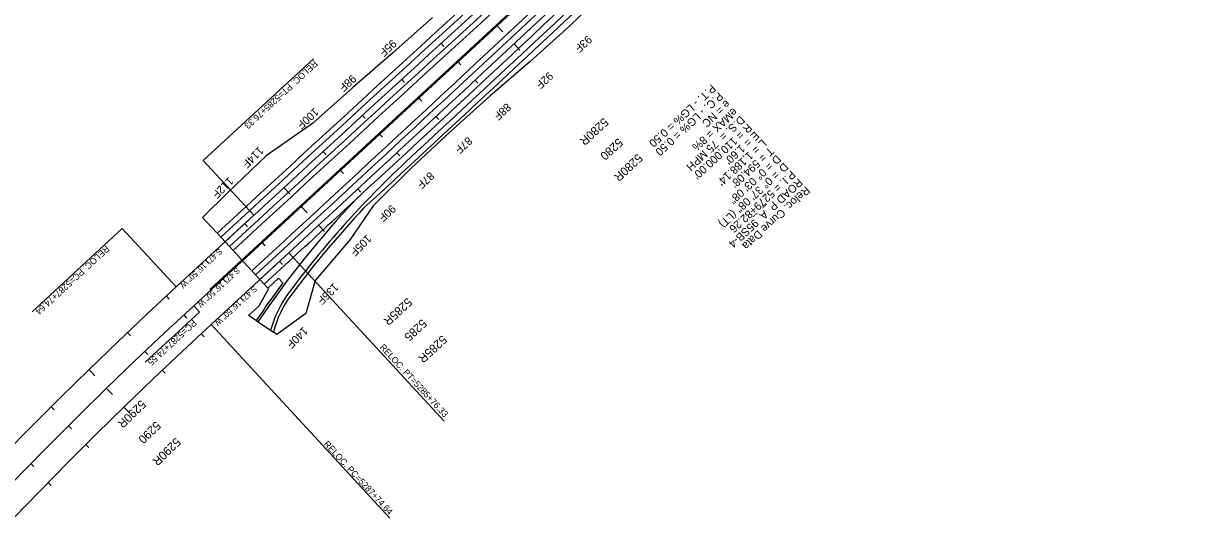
# Model space of a CAD drawing. Extents: x 2160876 to 2175625, y 601634 to 617693.
# Drawn here: x 2163386 to 2165605, y 605458 to 606388 of the extents above; entities that cross this region are included whole.
import ezdxf

# ---------------------------------------------------------------- set-up
doc = ezdxf.new("R2010")
doc.units = 0
for name, color, linetype in [('RD_HC_Cl', 7, 'Continuous'), ('RD_HC_CL_Rel', 7, 'Continuous'), ('RD_HC_Data', 7, 'Continuous'), ('RD_HC_Data_Rel', 7, 'Continuous'), ('RD_HC_Data_Tic', 7, 'Continuous'), ('RD_HC_Data_Tic_Rel', 7, 'Continuous'), ('RD_HC_TX_Rel_Sta50', 7, 'Continuous'), ('RD_HC_TX_Sta50', 7, 'Continuous'), ('RD_PD_CstnLmt', 7, 'Continuous'), ('RD_PD_Final_LnLine', 7, 'Continuous'), ('RD_PD_Final_TrvlWay', 7, 'Continuous'), ('RD_PD_GR', 7, 'Continuous')]:
    doc.layers.add(name, color=color, linetype=linetype)

msp = doc.modelspace()

# ---------------------------------------------------------------- linework, layer by layer
at = {"layer": 'RD_HC_Cl'}
msp.add_line((2172239.9, 613739.9), (2163704.8, 605858.6), dxfattribs=at)
msp.add_arc((2169535, 599544.7), 8593.9, 132.71947, 164.41949, dxfattribs=at)
at = {"layer": 'RD_HC_CL_Rel'}
for p, q in [((2163817.9, 606028.4), (2163672.2, 605893.8)), ((2163883.1, 605957.8), (2163737.4, 605823.3))]:
    msp.add_line(p, q, dxfattribs=at)
for centre, radius, start, end in [((2238443, 525213.1), 110000, 132.100607, 132.719474), ((2089258, 686773.1), 110000, 312.719474, 313.338341), ((2169535, 599544.7), 8641.9, 132.71947, 164.41949), ((2169535, 599544.7), 8545.9, 132.71947, 164.41949)]:
    msp.add_arc(centre, radius, start, end, dxfattribs=at)
at = {"layer": 'RD_HC_Data'}
for p, q in [((2163715.7, 605846.8), (2163613.6, 605752.5)), ((2163704.8, 605858.6), (2163715.7, 605846.8))]:
    msp.add_line(p, q, dxfattribs=at)
at = {"layer": 'RD_HC_Data_Rel'}
for p, q in [((2163722.9, 606131.3), (2163929.5, 606322)), ((2163722.9, 606131.3), (2163817.9, 606028.4)), ((2163571, 606003.4), (2163402.1, 605847.4)), ((2163571, 606003.4), (2163672.2, 605893.8)), ((2164174.5, 605642.2), (2163883.1, 605957.8)), ((2163737.4, 605823.3), (2164072.5, 605460.3))]:
    msp.add_line(p, q, dxfattribs=at)
at = {"layer": 'RD_HC_Data_Tic'}
for p, q in [((2164273.9, 606384), (2164284.7, 606372.3)), ((2164200.4, 606316.2), (2164205.8, 606310.3)), ((2164126.9, 606248.3), (2164132.3, 606242.5)), ((2164053.5, 606180.5), (2164058.9, 606174.6)), ((2163980, 606112.7), (2163985.4, 606106.8)), ((2163906.5, 606044.8), (2163917.4, 606033.1)), ((2163833, 605977), (2163838.5, 605971.1)), ((2163759.6, 605909.1), (2163765, 605903.3)), ((2163686.1, 605841.3), (2163691.6, 605835.4)), ((2163613.3, 605772.8), (2163618.8, 605767)), ((2163541.2, 605703.5), (2163552.4, 605692)), ((2163469.9, 605633.3), (2163475.6, 605627.6)), ((2163399.5, 605562.3), (2163405.2, 605556.7))]:
    msp.add_line(p, q, dxfattribs=at)
at = {"layer": 'RD_HC_Data_Tic_Rel'}
for p, q in [((2164168.6, 606350.7), (2164174, 606344.8)), ((2164305.5, 606349.9), (2164316.4, 606338.2)), ((2164094.9, 606283.2), (2164100.3, 606277.3)), ((2164232.3, 606281.7), (2164237.8, 606275.9)), ((2164021.2, 606215.6), (2164026.6, 606209.7)), ((2164159.1, 606213.6), (2164164.6, 606207.7)), ((2163947.6, 606147.9), (2163953, 606142)), ((2164085.8, 606145.5), (2164091.3, 606139.7)), ((2163874, 606080.1), (2163884.9, 606068.4)), ((2164012.5, 606077.6), (2164018, 606071.7)), ((2163800.5, 606012.3), (2163806, 606006.4)), ((2163939.1, 606009.6), (2163950, 605997.9)), ((2163727.1, 605944.5), (2163732.5, 605938.6)), ((2163865.7, 605941.8), (2163871.1, 605935.9)), ((2163653.6, 605876.6), (2163659.1, 605870.7)), ((2163792.2, 605873.9), (2163797.6, 605868.1)), ((2163580.8, 605808.1), (2163586.3, 605802.3)), ((2163718.8, 605806.1), (2163724.2, 605800.2)), ((2163508.7, 605738.8), (2163519.8, 605727.3)), ((2163645.9, 605737.6), (2163651.4, 605731.8)), ((2163437.4, 605668.6), (2163443.1, 605663)), ((2163573.8, 605668.2), (2163585, 605656.8)), ((2163502.6, 605598.1), (2163508.2, 605592.4)), ((2163432.2, 605527.1), (2163437.9, 605521.5))]:
    msp.add_line(p, q, dxfattribs=at)
at = {"layer": 'RD_PD_CstnLmt'}
for p, q in [((2164152.6, 606399.2), (2164077.9, 606332.8)), ((2164077.9, 606332.8), (2164002.4, 606267.1)), ((2164002.4, 606267.1), (2163927.7, 606200.7)), ((2163927.7, 606200.7), (2163841, 606140.1)), ((2163841, 606140.1), (2163768.7, 606071)), ((2163768.7, 606071), (2163721.5, 606024.2)), ((2163747.5, 605996), (2163721.5, 606024.2)), ((2163998.3, 605983.1), (2163932.8, 605905.8)), ((2163780, 605960.8), (2163812.7, 605925.5)), ((2163845.2, 605890.2), (2163826.8, 605858)), ((2163932.8, 605905.8), (2163915, 605844)), ((2163826.8, 605858), (2163807.5, 605840.2)), ((2163821.9, 605830.6), (2163807.5, 605840.2)), ((2163915, 605844), (2163860.8, 605804.7)), ((2163860.8, 605804.7), (2163854.2, 605809.1))]:
    msp.add_line(p, q, dxfattribs=at)
msp.add_lwpolyline([(2164878.1, 606761.5), (2164843.2, 606725.6), (2164806, 606692.2), (2164768.4, 606659.1), (2164729.9, 606627.2), (2164693.8, 606592.6), (2164655.6, 606560.2), (2164612.2, 606533.5), (2164562.8, 606513.4), (2164521, 606484.9), (2164446.2, 606418.5), (2164410.1, 606383.9), (2164335.8, 606317), (2164259.9, 606251.7), (2164185.8, 606184.6), (2164112.5, 606116.5), (2164041.3, 606046.2), (2163998.3, 605983.1)], dxfattribs=at)
at = {"layer": 'RD_PD_Final_LnLine'}
for p, q in [((2163809.8, 606037.2), (2163755.7, 605987.2)), ((2163817.9, 606028.4), (2163763.8, 605978.4)), ((2163826.1, 606019.5), (2163772, 605969.6)), ((2163874.9, 605966.6), (2163820.8, 605916.7)), ((2163883.1, 605957.8), (2163828.9, 605907.9)), ((2163891.2, 605949), (2163837.1, 605899))]:
    msp.add_line(p, q, dxfattribs=at)
for centre, radius, start, end in [((2238443, 525213.1), 110012, 132.100607, 132.719474), ((2238443, 525213.1), 110000, 132.100607, 132.719474), ((2238443, 525213.1), 109988, 132.100607, 132.719474), ((2089258, 686773.1), 109988, 312.719474, 313.338341), ((2089258, 686773.1), 110000, 312.719474, 313.338341), ((2089258, 686773.1), 110012, 312.802799, 313.338341), ((2089258, 686773.1), 110024, 312.863734, 313.338341), ((2165306.8, 604831), 1770, 132.8638, 143.5951), ((2165306.8, 604831), 1786, 136.6199, 146.0495), ((2089258, 686773.1), 110012, 312.719474, 312.802799), ((2164048.7, 605758.6), 206.9, 143.5951, 164.8838)]:
    msp.add_arc(centre, radius, start, end, dxfattribs=at)
at = {"layer": 'RD_PD_Final_TrvlWay'}
for p, q in [((2163803, 606044.5), (2163748.9, 605994.5)), ((2163832.9, 606012.2), (2163778.7, 605962.2)), ((2163780.1, 605960.7), (2163748.9, 605994.5)), ((2163868.1, 605974), (2163814, 605924)), ((2163843.9, 605891.7), (2163814, 605924)), ((2163864, 605910.3), (2163843.9, 605891.7)), ((2163864, 605910.3), (2163872.2, 605901.5)), ((2163821.9, 605830.6), (2163854.2, 605809.1))]:
    msp.add_line(p, q, dxfattribs=at)
for centre, radius, start, end in [((2238443, 525213.1), 110022, 132.100607, 132.719474), ((2238443, 525213.1), 109978, 132.100607, 132.719474), ((2089258, 686773.1), 109978, 312.719474, 313.338341), ((2089258, 686773.1), 110034, 312.803121, 313.338341), ((2165306.8, 604831), 1764, 136.6475, 143.5951), ((2165306.8, 604831), 1790, 143.2688, 146.0495), ((2164048.7, 605758.6), 200.9, 143.5951, 165.4609)]:
    msp.add_arc(centre, radius, start, end, dxfattribs=at)
at = {"layer": 'RD_PD_GR'}
msp.add_line((2165000.3, 607057.6), (2163734.9, 605889.1), dxfattribs=at)

# ---------------------------------------------------------------- texts
at = {"layer": 'RD_HC_Data'}
for s, height, p in [('S 47° 16\' 50" W', 10.8, (2163785.5, 605930.9)), ('PC=5287+74.55', 12, (2163703.5, 605833.3))]:
    msp.add_text(s, height=height, rotation=222.7195, dxfattribs=at).set_placement(p)
at = {"layer": 'RD_HC_Data_Rel'}
for s, height, rotation, p in [('RELOC. PT=5285+76.33', 12, 222.7195, (2163930.5, 606319.6)), ('P.T. - LG% = 0.50', 15, 222.7195, (2164675.5, 606274.9)), ('P.C. - LG% = 0.50', 15, 222.7195, (2164689.1, 606260.2)), ('eMAX = 8%', 15, 222.7195, (2164716.2, 606230.8)), ('e = NC', 15, 222.7195, (2164702.6, 606245.5)), ('D.S. =  75 MPH', 15, 222.7195, (2164729.8, 606216.1)), ("R = 110,000.00'", 15, 222.7195, (2164743.4, 606201.4)), ("E = 1.60'", 15, 222.7195, (2164756.9, 606186.7)), ("L = 1,188.14'", 15, 222.7195, (2164770.5, 606172)), ('D = 0° 03\' 08"', 15, 222.7195, (2164797.6, 606142.7)), ("T = 594.08'", 15, 222.7195, (2164784.1, 606157.4)), ('P.I. = 5279+82.26', 15, 222.7195, (2164824.8, 606113.3)), ('D', 15, 222.7195, (2164811.2, 606128)), ('    = 0° 37\' 08" (LT)', 15, 222.7195, (2164811.2, 606128)), ('ROAD P_A_95SB-4', 15, 222.7195, (2164838.3, 606098.6)), ('Reloc. Curve Data', 15, 222.7195, (2164851.9, 606083.9)), ('RELOC. PC=5287+74.64', 12, 222.7195, (2163540.2, 605972.3)), ('S 47° 16\' 50" W', 10.8, 222.7195, (2163752.5, 605967.1)), ('S 47° 16\' 50" W', 10.8, 222.7195, (2163817.5, 605896.5)), ('RELOC. PT=5285+76.33', 12, 312.7195, (2164052.7, 605779.9)), ('RELOC. PC=5287+74.64', 12, 312.7195, (2163947.8, 605598.3))]:
    msp.add_text(s, height=height, rotation=rotation, dxfattribs=at).set_placement(p)
at = {"layer": 'RD_HC_TX_Rel_Sta50'}
for s, rotation, p in [('5280R', 222.4193, (2164473.6, 606212.3)), ('5280R', 223.0197, (2164537.3, 606145)), ('5285R', 222.6797, (2164105.5, 605874.6)), ('5285R', 222.7592, (2164170.7, 605804.3)), ('5290R', 224.2136, (2163606, 605682.8)), ('5290R', 224.2304, (2163671.2, 605612.3))]:
    msp.add_text(s, height=16, rotation=rotation, dxfattribs=at).set_placement(p)
at = {"layer": 'RD_HC_TX_Sta50'}
for s, rotation, p in [('5280', 222.7195, (2164500.6, 606174.1)), ('5285', 222.7195, (2164132.9, 605834.6)), ('5290', 224.2225, (2163633.8, 605642.9))]:
    msp.add_text(s, height=16, rotation=rotation, dxfattribs=at).set_placement(p)
at = {"layer": 'RD_PD_CstnLmt'}
for s, rotation, p in [('95F', 222.5234, (2164076.9, 606359)), ('93F', 222.5234, (2164443.2, 606366.7)), ('98F', 222.5234, (2164001.4, 606293.3)), ('92F', 222.5234, (2164370.5, 606298.4)), ('100F', 222.5234, (2163930.9, 606230.7)), ('88F', 222.5234, (2164291.4, 606239.7)), ('114F', 225.0629, (2163826.9, 606158.3)), ('87F', 222.5234, (2164218.8, 606176.6)), ('112F', 225.0629, (2163770.5, 606101.1)), ('87F', 222.5234, (2164147.5, 606110.9)), ('90F', 222.5234, (2164075.5, 606049.1)), ('105F', 225.0629, (2164029.4, 605993.1)), ('136F', 225.0629, (2163967.5, 605902.2)), ('140F', 225.0629, (2163910.1, 605820))]:
    msp.add_text(s, height=15, rotation=rotation, dxfattribs=at).set_placement(p)

doc.saveas('drawing.dxf')
